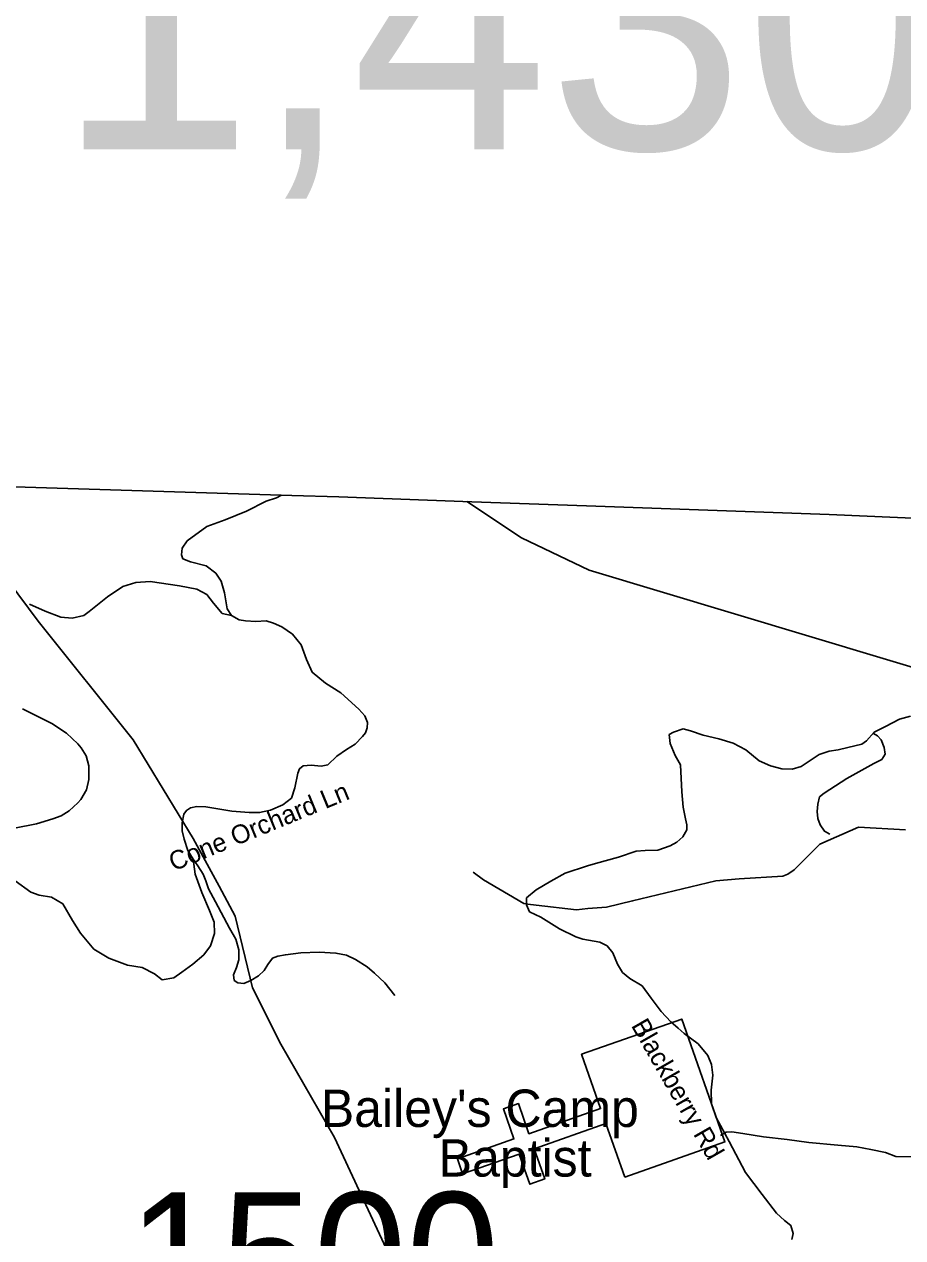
# Model space of a CAD drawing. Extents: x 1159738 to 1321356, y 736314 to 882035.
# Drawn here: x 1216229 to 1219753, y 869455 to 874325 of the extents above; entities that cross this region are included whole.
import ezdxf

# ---------------------------------------------------------------- set-up
doc = ezdxf.new("R2010")
doc.units = 0
for name, color, linetype in [('Exist Boundary Political CountyLine', 7, 'Continuous'), ('Exist Civil Demographics City Label', 7, 'Continuous'), ('Exist Cultural Church CELL', 7, 'Continuous'), ('Exist Cultural Church Label', 7, 'Continuous'), ('Exist Hydrographic Creek Single Shore', 7, 'Continuous'), ('Exist Hydrographic Misc Water Feature', 7, 'Continuous'), ('Exist Road Non-System Type 51', 7, 'Continuous'), ('Exist Road Non-System Type 51 Label', 7, 'Continuous'), ('Exist Road Primary US Attributed', 7, 'Continuous'), ('Exist Road Secondary Type 51 Attributed', 7, 'Continuous'), ('Exist Road Secondary Type 51 Label', 7, 'Continuous'), ('Exist Road Secondary Type 51 Number Label', 7, 'Continuous'), ('Exist Utilities Electrical Transmission Line', 7, 'Continuous')]:
    doc.layers.add(name, color=color, linetype=linetype)

msp = doc.modelspace()

# ---------------------------------------------------------------- linework, layer by layer
at = {"layer": 'Exist Boundary Political CountyLine'}
msp.add_lwpolyline([(1214222.1, 872529.9), (1217303, 872434), (1217490.7, 872427.7), (1218024.4, 872408.6), (1218484.1, 872392.2), (1219457.7, 872357.9), (1220250.2, 872322.9), (1220294.9, 872320.9), (1220446.8, 872314.3), (1221790.2, 872268.7), (1222842.2, 872227.9), (1223507.1, 872202.2), (1223620.3, 872197.8), (1224130.5, 872178.2), (1224389.7, 872170.5), (1231200.8, 871901.6), (1233216.1, 871828.8), (1237047.9, 871704.9), (1245972.1, 871384.1), (1248224.3, 871303)], dxfattribs=at)
at = {"layer": 'Exist Cultural Church CELL'}
msp.add_lwpolyline([(1218638.3, 869698.3), (1218562.3, 869913), (1218275, 869812.1), (1218317.4, 869691.3), (1218257.1, 869670.1), (1218214.7, 869790.9), (1217987.7, 869711.1), (1217966.5, 869771.6), (1218193.5, 869851.4), (1218151, 869972.1), (1218211.3, 869993.3), (1218253.7, 869872.5), (1218541.1, 869973.5), (1218465, 870191.2), (1218866.8, 870332.4), (1219040, 869839.5)], close=True, dxfattribs=at)
at = {"layer": 'Exist Hydrographic Creek Single Shore'}
msp.add_lwpolyline([(1224113.2, 870488.1), (1223644.6, 870529.5), (1222860.1, 870729.9), (1222678.7, 870801.8), (1222461.2, 870909), (1221787, 871125.6), (1221663.1, 871154.3), (1221455.7, 871191.6), (1221179.8, 871217.6), (1220917.4, 871258.5), (1220702.5, 871302), (1220588.9, 871445), (1220329.2, 871574.9), (1219959.1, 871694), (1218495, 872133.6), (1218224.1, 872263.8), (1218004.9, 872409.3)], dxfattribs=at)
at = {"layer": 'Exist Hydrographic Misc Water Feature'}
msp.add_lwpolyline([(1218030.2, 870922.3), (1218071.4, 870891.2), (1218233, 870796.7), (1218249, 870794.3), (1218282.8, 870789.5), (1218444.4, 870771), (1218490.5, 870775.8), (1218564.9, 870781.8), (1218669.5, 870806.9), (1219004, 870888), (1219004, 870888), (1219096.4, 870895.5), (1219272.7, 870906.7), (1219292.9, 870914.1), (1219317.4, 870931.6), (1219420.3, 871034.8), (1219576.2, 871102.6), (1219576.2, 871102.6), (1219764.1, 871091.5)], dxfattribs=at)
at = {"layer": 'Exist Road Non-System Type 51'}
for points in [[(1217715.7, 870427.6), (1217675.5, 870478.4), (1217634.2, 870517.4), (1217604.7, 870542.2), (1217557.5, 870571.7), (1217522.1, 870589.4), (1217479.7, 870597.7), (1217412.4, 870601.2), (1217338.1, 870598.8), (1217276.7, 870590.6), (1217246, 870584.7), (1217224.8, 870576.4), (1217205.9, 870551.6), (1217191.8, 870528), (1217168.2, 870505.6), (1217138.7, 870487.9), (1217110.3, 870476), (1217085.6, 870478.4), (1217071.4, 870487.9), (1217069, 870510.3), (1217080.8, 870539.8), (1217090.3, 870570.5), (1217090.3, 870610.7), (1217077.3, 870653.2), (1217052.5, 870698), (1216995.9, 870803.1), (1216968, 870855.6), (1216957.4, 870887.4), (1216946.8, 870914.6), (1216925.6, 870947.7), (1216906.7, 870974.8), (1216885.4, 871009.1), (1216870.1, 871055.1), (1216863, 871088.2), (1216863, 871120), (1216868.9, 871154.3), (1216879.5, 871169.6), (1216896.1, 871180.3), (1216920.8, 871185), (1216957.4, 871183.8), (1217061.2, 871167.3), (1217130.9, 871161.4), (1217173.3, 871161.4), (1217217, 871170.8), (1217266.6, 871192.1), (1217300.8, 871219.2), (1217314.7, 871260.1), (1217326.5, 871319.1), (1217333.6, 871336.8), (1217347.7, 871348.6), (1217379.6, 871351), (1217419.7, 871347.5), (1217446.8, 871353.4), (1217483.4, 871387.6), (1217522.4, 871414.8), (1217556.6, 871436), (1217585.7, 871466.2), (1217598.7, 871481.6), (1217604.6, 871501.6), (1217605.8, 871522.9), (1217595.1, 871548.9), (1217571.5, 871576), (1217499.6, 871642.1), (1217437, 871679.9), (1217384.1, 871724.4), (1217361.7, 871775.2), (1217340.5, 871834.2), (1217305.1, 871876.7), (1217262.6, 871906.2), (1217228.4, 871921.6), (1217200.1, 871931), (1217158.8, 871927.5), (1217116.3, 871931), (1217091.5, 871934.6), (1217060, 871951.7), (1217043.5, 871978.9), (1217032.9, 872042.7), (1217018.7, 872089.9), (1216997.5, 872121.8), (1216958.6, 872151.3), (1216896, 872167.8), (1216865.4, 872179.6), (1216859.5, 872195), (1216863, 872222.1), (1216883.1, 872251.7), (1216962.1, 872309.5), (1217035.3, 872335.5), (1217120.2, 872370.9), (1217199.3, 872411.1), (1217241.6, 872424.8), (1217261.3, 872435.3)], [(1217060, 871951.7), (1217023.5, 871959.9), (1216987.7, 872001.5), (1216962, 872035.8), (1216921.7, 872057.3), (1216851.6, 872070.7), (1216734.1, 872088), (1216676.9, 872084.2), (1216624.9, 872068.1), (1216563.6, 872026.8), (1216490.2, 871967.8), (1216468.1, 871952.4), (1216421, 871941.3), (1216376.1, 871945.3), (1216313.3, 871968.8), (1216250.3, 871997.3)], [(1219636, 871479), (1219651.5, 871468.6), (1219667, 871453.1), (1219679, 871422.1), (1219682.5, 871396.3), (1219668.7, 871373.9), (1219637.7, 871358.4), (1219529.3, 871298.1), (1219438, 871239.5), (1219419.1, 871224), (1219412.2, 871194.7), (1219410.5, 871165.5), (1219412.2, 871137.9), (1219422.6, 871112.1), (1219439.8, 871086.2), (1219460.4, 871074.2)], [(1216906.7, 870974.8), (1216914.8, 870914.1), (1216941.4, 870839.9), (1216972.9, 870768.3), (1216991.4, 870721.3), (1216992.4, 870676.4), (1216976.1, 870626.2), (1216949.5, 870590.7), (1216905.5, 870552.3), (1216861.3, 870521.4), (1216829.5, 870498.2), (1216782.3, 870489.7), (1216751.9, 870514), (1216701.5, 870540.2), (1216644, 870548.9), (1216568.6, 870577.2), (1216508, 870613.2), (1216454.2, 870676.8), (1216423.2, 870728.5), (1216384.3, 870794.9), (1216338.9, 870821.3), (1216288.8, 870830.2), (1216256.2, 870841.9), (1216192.9, 870887.9)], [(1219022.4, 869864.8), (1219044.8, 869878.2), (1219067.2, 869880.5), (1219112, 869873.8), (1219194.9, 869860.3), (1219289.1, 869849.1), (1219376.5, 869837.9), (1219493, 869826.7), (1219569.2, 869819.9), (1219625.3, 869808.7), (1219683.6, 869797.5), (1219726.1, 869781.8), (1219788.9, 869779.5)]]:
    msp.add_lwpolyline(points, dxfattribs=at)
at = {"layer": 'Exist Road Primary US Attributed'}
msp.add_lwpolyline([(1216190.3, 871098.3), (1216278, 871115.8), (1216344.2, 871135.8), (1216376.9, 871148.5), (1216409.6, 871168.5), (1216443.5, 871200.8), (1216456.3, 871213.5), (1216479.4, 871252.6), (1216488.4, 871293.7), (1216487.6, 871348.9), (1216476.9, 871388.4), (1216458, 871420.5), (1216444.4, 871436.7), (1216398.4, 871480.5), (1216340.3, 871518.4), (1216221.6, 871577.6)], dxfattribs=at)
at = {"layer": 'Exist Road Secondary Type 51 Attributed'}
for points in [[(1218882.4, 871135.5), (1218872.9, 871183.1), (1218867.2, 871244), (1218861.5, 871352.4), (1218840.6, 871390.5), (1218819.7, 871438), (1218815.9, 871474.2), (1218833, 871483.7), (1218872.9, 871497), (1218901.5, 871489.4), (1218952.8, 871472.3), (1219015.5, 871457.1), (1219072.5, 871439.9), (1219123.9, 871413.3), (1219177.1, 871369.5), (1219222.7, 871348.6), (1219268.4, 871337.2), (1219310.2, 871335.3), (1219345.4, 871346.4), (1219417.6, 871394), (1219457.5, 871407.3), (1219493.7, 871413), (1219533.6, 871422.6), (1219588.7, 871435.9), (1219607.7, 871449.2), (1219638.1, 871483.4), (1219683.8, 871506.3), (1219740.8, 871536.7), (1219784.5, 871548.1)], [(1218520.1, 870956.3), (1218612.7, 870982.6), (1218683.2, 871006.7), (1218720.3, 871008.6), (1218770.4, 871010.5), (1218820.5, 871027.2), (1218846.5, 871042), (1218870.7, 871064.3), (1218887.4, 871092.2), (1218887.4, 871112.6), (1218882.4, 871135.5)], [(1218784.7, 870363.4), (1218771.9, 870379.7), (1218744, 870416.9), (1218707.3, 870466.2), (1218659.1, 870495.9), (1218629.4, 870520), (1218608.9, 870553.5), (1218590.4, 870598.1), (1218568.1, 870625.9), (1218538.4, 870640.8), (1218469.7, 870653.8), (1218441.9, 870663.1), (1218376.9, 870694.7), (1218300.8, 870741.1), (1218256.3, 870763.4), (1218243.3, 870791.2), (1218243.3, 870819.1), (1218282.3, 870850.7), (1218341.7, 870886), (1218399.2, 870917.6), (1218488.3, 870947.3), (1218520.1, 870956.3)], [(1219308.7, 869448.1), (1219314.2, 869472.3), (1219304.9, 869503.9), (1219279, 869524.3), (1219247.4, 869554), (1219189.9, 869628.3), (1219123, 869717.5), (1219056.7, 869840.7), (1219004.7, 869937.3), (1218986.2, 869993), (1218984.3, 870046.9), (1218991.7, 870108.2), (1218986.2, 870151), (1218971.3, 870186.2), (1218932.3, 870232.7), (1218876.6, 870275.4), (1218852.5, 870295.8), (1218822.8, 870321.9), (1218784.7, 870363.4)]]:
    msp.add_lwpolyline(points, dxfattribs=at)
at = {"layer": 'Exist Utilities Electrical Transmission Line'}
for points in [[(1215954, 872476.4), (1215957.9, 872462.7), (1216043.5, 872253.5), (1216284.4, 871929.2), (1216665.4, 871453.8), (1216906.2, 871057)], [(1216906.2, 871057), (1217011.2, 870865.8), (1217074.7, 870746.2)], [(1217074.7, 870746.2), (1217145.3, 870458.5), (1217259.1, 870232.4), (1217473.6, 869857.7), (1217681.4, 869412), (1217951.2, 868831.3), (1217984.9, 868756.5)]]:
    msp.add_lwpolyline(points, dxfattribs=at)

# ---------------------------------------------------------------- texts
at = {"layer": 'Exist Civil Demographics City Label'}
msp.add_text('Pop. 1,430', height=1060, dxfattribs=at).set_placement((1213050.2, 873822.5))
at = {"layer": 'Exist Cultural Church Label'}
for s, p in [("Bailey's Camp", (1217419, 869899.8)), ('Baptist', (1217891.7, 869700.6))]:
    msp.add_text(s, height=150, dxfattribs=at).set_placement(p)
at = {"layer": 'Exist Road Non-System Type 51 Label'}
msp.add_text('Cone Orchard Ln', height=75, rotation=22.3366, dxfattribs=at).set_placement((1216828.2, 870924.9))
at = {"layer": 'Exist Road Secondary Type 51 Label'}
msp.add_text('Blackberry Rd', height=75, rotation=299.8153, dxfattribs=at).set_placement((1218661.8, 870306.9))
at = {"layer": 'Exist Road Secondary Type 51 Number Label'}
msp.add_text('1500', height=500, dxfattribs=at).set_placement((1216647, 869137.8))

doc.saveas('drawing.dxf')
